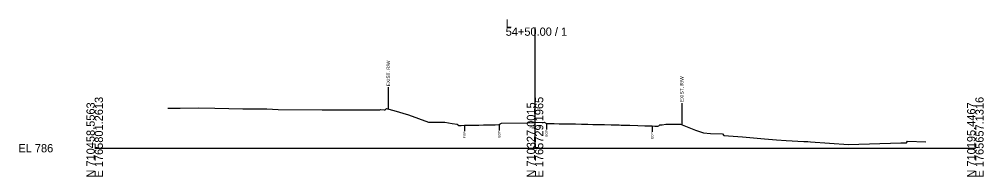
# Model space of a CAD drawing. Extents: x -26 to 5303, y -10 to 9578.
# Drawn here: x 3974.3 to 4302.8, y 4490.3 to 4543.9 of the extents above; entities that cross this region are included whole.
import ezdxf

# ---------------------------------------------------------------- set-up
doc = ezdxf.new("R2010")
doc.units = 0
for name, color, linetype in [('Exist Cross Section Cell', 7, 'Continuous'), ('Exist XS Ground Line', 7, 'Continuous'), ('Old_Level_10', 7, 'Continuous'), ('Old_Level_3', 7, 'Continuous')]:
    doc.layers.add(name, color=color, linetype=linetype)

msp = doc.modelspace()

# ---------------------------------------------------------------- linework, layer by layer
at = {"layer": 'Exist Cross Section Cell'}
for p, q in [((4150, 4500), (4150, 4541.07)), ((4000, 4500), (4150, 4500)), ((4150, 4500), (4300, 4500))]:
    msp.add_line(p, q, dxfattribs=at)
at = {"layer": 'Exist XS Ground Line'}
msp.add_lwpolyline([(4024.91, 4513.59), (4025.95, 4513.63), (4029.13, 4513.67), (4035.33, 4513.69), (4040.89, 4513.61), (4050.42, 4513.41), (4058.67, 4513.39), (4062.53, 4513.22), (4077.51, 4513.01), (4083.32, 4513.05), (4095.25, 4513.07), (4097.09, 4513.04), (4097.41, 4513.12), (4098.58, 4513.06), (4098.91, 4513.04), (4099.41, 4513.54), (4099.77, 4513.42), (4101.95, 4512.88), (4106.93, 4511.31), (4113.72, 4508.89), (4116.13, 4508.89), (4119.23, 4508.89), (4121.77, 4508.45), (4123.43, 4508.18), (4124.02, 4507.72), (4124.85, 4507.76), (4126, 4507.81), (4127.38, 4507.84), (4128.05, 4507.85), (4130.11, 4507.88), (4130.9, 4507.89), (4132.47, 4507.94), (4133.75, 4507.96), (4134.31, 4507.96), (4135.32, 4507.98), (4136.41, 4508.01), (4137.77, 4508.07), (4138.17, 4508.29), (4138.58, 4508.51), (4147.6, 4508.69), (4150, 4508.74), (4153.08, 4508.81), (4153.9, 4508.42), (4154.8, 4508.39), (4155.35, 4508.38), (4156.56, 4508.37), (4158.25, 4508.34), (4159.41, 4508.33), (4161.34, 4508.31), (4162.26, 4508.29), (4163.77, 4508.26), (4165.86, 4508.17), (4166.42, 4508.16), (4167.96, 4508.14), (4169.68, 4508.1), (4170.81, 4508.08), (4171.74, 4508.07), (4173.66, 4508.05), (4175.98, 4507.98), (4176.62, 4507.96), (4177.44, 4507.9), (4178.09, 4507.91), (4178.67, 4507.9), (4179.36, 4507.89), (4182.29, 4507.82), (4185.06, 4507.73), (4187.35, 4507.65), (4187.91, 4507.63), (4189.16, 4507.59), (4189.9, 4507.58), (4190.81, 4507.52), (4191.86, 4507.45), (4192.16, 4507.66), (4192.48, 4507.92), (4193.28, 4507.99), (4194.54, 4508.16), (4197.68, 4508.16), (4199.54, 4508.16), (4204.64, 4506.16), (4207.36, 4505.19), (4209.79, 4505), (4213.91, 4504.85), (4214.33, 4504.35), (4220.67, 4503.82), (4228.18, 4503.22), (4232.25, 4502.9), (4235.55, 4502.65), (4241.57, 4502.33), (4242.92, 4502.26), (4243.85, 4502.2), (4256.78, 4501.25), (4274.58, 4501.81), (4276.02, 4501.86), (4276.51, 4501.86), (4276.92, 4502.36), (4283.1, 4502.2)], dxfattribs=at)
at = {"layer": 'Old_Level_10'}
for p, q in [((4100, 4520.76), (4100, 4513.36)), ((4200, 4515.38), (4200, 4507.98)), ((4126, 4507.81), (4126, 4505.76)), ((4137.77, 4508.07), (4137.77, 4506.02)), ((4153.9, 4508.42), (4153.9, 4506.37)), ((4189.9, 4507.58), (4189.9, 4505.53))]:
    msp.add_line(p, q, dxfattribs=at)

# ---------------------------------------------------------------- texts
at = {"layer": 'Exist Cross Section Cell'}
for s, p in [('L', (4140, 4541.07)), ('54+50.00 / 1', (4140, 4538.27)), ('EL 786', (3974, 4498.6))]:
    msp.add_text(s, height=2.8, dxfattribs=at).set_placement(p)
for s, p in [('E 1765729.1965', (4152.8, 4490)), ('N 710458.5563', (4000, 4490)), ('E 1765801.2613', (4002.8, 4490)), ('N 710327.0015', (4150, 4490)), ('N 710195.4467', (4300, 4490)), ('E 1765657.1316', (4302.8, 4490))]:
    msp.add_text(s, height=2.8, rotation=90, dxfattribs=at).set_placement(p)
at = {"layer": 'Old_Level_10'}
for s, height, p in [('EXIST. R/W', 1.181, (4100.59, 4521.06)), ('EXIST. R/W', 1.181, (4200.59, 4515.68)), ('EOP', 0.787, (4126.4, 4503.36)), ('EOP', 0.787, (4138.17, 4503.62)), ('EOP', 0.787, (4154.3, 4503.97)), ('EOP', 0.787, (4190.29, 4503.13))]:
    msp.add_text(s, height=height, rotation=90, dxfattribs=at).set_placement(p)
at = {"layer": 'Old_Level_3'}
msp.add_text('794.74', height=1, dxfattribs=at).set_placement((4147.95, 4506.74))

doc.saveas('drawing.dxf')
